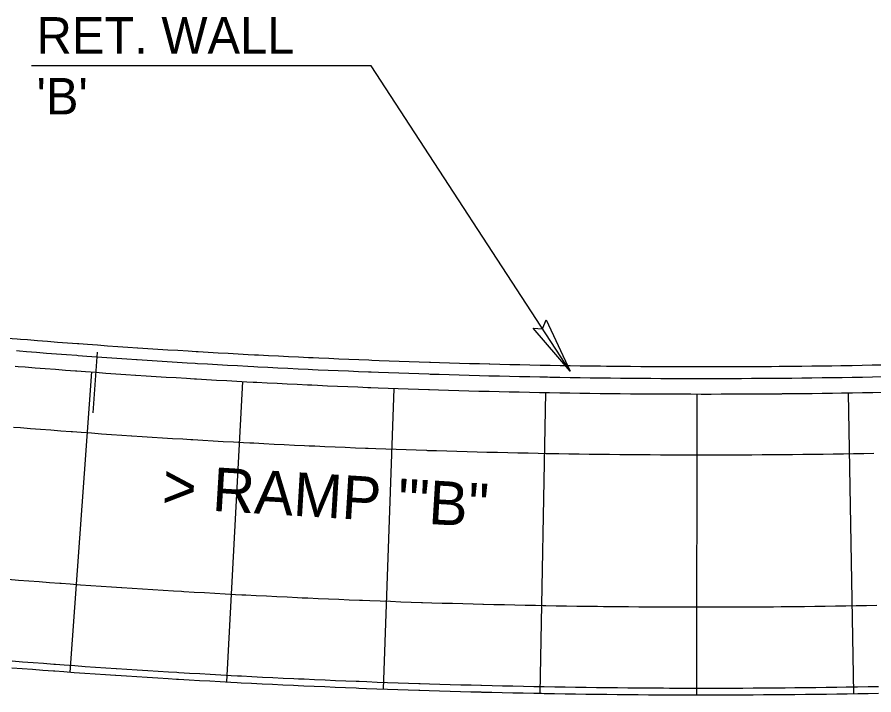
# Model space of a CAD drawing. Extents: x 2145147 to 2158018, y 137519 to 148068.
# Drawn here: x 2151017.9 to 2151102.3, y 142316.6 to 142383.4 of the extents above; entities that cross this region are included whole.
import ezdxf

# ---------------------------------------------------------------- set-up
doc = ezdxf.new("R2010")
doc.units = 0
for name, color, linetype in [('PR_Align_Ramp_B', 7, 'Continuous'), ('PR_Align_Ramp_B_Label', 7, 'Continuous'), ('PR_Align_Service_C_Leader', 7, 'Continuous'), ('PR_Align_Service_C_Txt', 7, 'Continuous'), ('PR_Arrows', 7, 'Continuous'), ('PR_Curb_Back', 7, 'Continuous'), ('PR_Curb_Face', 7, 'Continuous'), ('PR_Joint_Contraction', 7, 'Continuous'), ('PR_Joint_Long', 7, 'Continuous'), ('PR_Parapet', 7, 'Continuous'), ('PR_Retaining_Wall', 7, 'Continuous')]:
    doc.layers.add(name, color=color, linetype=linetype)

msp = doc.modelspace()

# ---------------------------------------------------------------- linework, layer by layer
at = {"layer": 'PR_Align_Ramp_B'}
msp.add_lwpolyline([(2151025.769, 142350.363), (2151025.342, 142344.378)], dxfattribs=at)
at = {"layer": 'PR_Align_Service_C_Leader'}
msp.add_lwpolyline([(2151072.395, 142348.47), (2151052.784, 142378.577), (2151019.318, 142378.577)], dxfattribs=at)
at = {"layer": 'PR_Arrows'}
msp.add_lwpolyline([(2151072.395, 142348.47), (2151068.731, 142352.723), (2151069.673, 142352.648), (2151070.02, 142353.552)], close=True, dxfattribs=at)
at = {"layer": 'PR_Curb_Back'}
msp.add_lwpolyline([(2151017.352, 142319.238), (2151018.379, 142319.158), (2151019.406, 142319.079), (2151020.433, 142319.002), (2151021.461, 142318.926), (2151021.603, 142318.915), (2151022.488, 142318.85), (2151023.516, 142318.776), (2151024.543, 142318.704), (2151025.571, 142318.632), (2151026.599, 142318.562), (2151027.593, 142318.495), (2151027.627, 142318.493), (2151028.655, 142318.425), (2151029.683, 142318.358), (2151030.711, 142318.293), (2151031.739, 142318.229), (2151032.768, 142318.166), (2151033.584, 142318.117), (2151033.796, 142318.104), (2151034.825, 142318.043), (2151035.853, 142317.984), (2151036.882, 142317.926), (2151037.91, 142317.869), (2151038.939, 142317.813), (2151039.579, 142317.779), (2151039.968, 142317.758), (2151040.997, 142317.705), (2151042.026, 142317.653), (2151043.055, 142317.602), (2151044.084, 142317.552), (2151045.113, 142317.504), (2151045.575, 142317.483), (2151046.142, 142317.457), (2151047.171, 142317.411), (2151048.2, 142317.366), (2151049.23, 142317.322), (2151050.259, 142317.28), (2151051.288, 142317.239), (2151051.574, 142317.227), (2151052.318, 142317.199), (2151053.347, 142317.16), (2151054.377, 142317.122), (2151055.407, 142317.086), (2151056.436, 142317.051), (2151057.466, 142317.017), (2151057.574, 142317.013), (2151058.496, 142316.984), (2151059.525, 142316.953), (2151060.555, 142316.922), (2151061.585, 142316.893), (2151062.615, 142316.865), (2151063.575, 142316.841), (2151063.645, 142316.839), (2151064.675, 142316.813), (2151065.705, 142316.789), (2151066.735, 142316.766), (2151067.765, 142316.744), (2151068.795, 142316.724), (2151069.577, 142316.709), (2151069.825, 142316.704), (2151070.855, 142316.686), (2151071.885, 142316.669), (2151072.915, 142316.654), (2151073.945, 142316.639), (2151074.975, 142316.626), (2151075.58, 142316.619), (2151076.005, 142316.614), (2151077.036, 142316.603), (2151078.066, 142316.593), (2151079.096, 142316.585), (2151080.126, 142316.577), (2151081.156, 142316.571), (2151081.584, 142316.569), (2151082.187, 142316.567), (2151083.217, 142316.563), (2151084.247, 142316.561), (2151085.277, 142316.56), (2151086.308, 142316.56), (2151087.338, 142316.561), (2151087.588, 142316.561), (2151088.368, 142316.563), (2151089.398, 142316.567), (2151090.429, 142316.572), (2151091.459, 142316.578), (2151092.489, 142316.585), (2151093.251, 142316.592), (2151093.519, 142316.594), (2151093.591, 142316.595), (2151094.549, 142316.604), (2151095.58, 142316.615), (2151096.61, 142316.627), (2151097.64, 142316.64), (2151098.67, 142316.655), (2151099.595, 142316.669), (2151099.7, 142316.671), (2151100.73, 142316.688), (2151101.76, 142316.706), (2151102.79, 142316.726)], dxfattribs=at)
at = {"layer": 'PR_Curb_Face'}
msp.add_lwpolyline([(2151017.404, 142319.903), (2151018.43, 142319.823), (2151019.456, 142319.744), (2151020.483, 142319.667), (2151021.51, 142319.59), (2151021.652, 142319.58), (2151022.536, 142319.515), (2151023.563, 142319.441), (2151024.59, 142319.369), (2151025.617, 142319.297), (2151026.644, 142319.227), (2151027.637, 142319.16), (2151027.671, 142319.158), (2151028.698, 142319.09), (2151029.726, 142319.024), (2151030.753, 142318.958), (2151031.781, 142318.894), (2151032.808, 142318.831), (2151033.624, 142318.782), (2151033.836, 142318.769), (2151034.863, 142318.709), (2151035.891, 142318.649), (2151036.919, 142318.591), (2151037.947, 142318.534), (2151038.975, 142318.479), (2151039.614, 142318.445), (2151040.003, 142318.424), (2151041.031, 142318.371), (2151042.059, 142318.319), (2151043.087, 142318.268), (2151044.115, 142318.218), (2151045.144, 142318.17), (2151045.606, 142318.149), (2151046.172, 142318.123), (2151047.2, 142318.077), (2151048.229, 142318.032), (2151049.257, 142317.988), (2151050.286, 142317.946), (2151051.315, 142317.905), (2151051.6, 142317.894), (2151052.343, 142317.865), (2151053.372, 142317.826), (2151054.401, 142317.788), (2151055.43, 142317.752), (2151056.459, 142317.717), (2151057.487, 142317.683), (2151057.595, 142317.68), (2151058.516, 142317.65), (2151059.545, 142317.619), (2151060.574, 142317.589), (2151061.603, 142317.56), (2151062.632, 142317.532), (2151063.592, 142317.507), (2151063.662, 142317.505), (2151064.691, 142317.48), (2151065.72, 142317.456), (2151066.749, 142317.433), (2151067.778, 142317.411), (2151068.808, 142317.39), (2151069.59, 142317.375), (2151069.837, 142317.371), (2151070.866, 142317.353), (2151071.895, 142317.336), (2151072.925, 142317.32), (2151073.954, 142317.306), (2151074.983, 142317.292), (2151075.588, 142317.285), (2151076.013, 142317.28), (2151077.042, 142317.269), (2151078.072, 142317.26), (2151079.101, 142317.251), (2151080.13, 142317.244), (2151081.16, 142317.238), (2151081.587, 142317.236), (2151082.189, 142317.233), (2151083.219, 142317.23), (2151084.248, 142317.227), (2151085.278, 142317.226), (2151086.307, 142317.226), (2151087.337, 142317.228), (2151087.586, 142317.228), (2151088.366, 142317.23), (2151089.396, 142317.234), (2151090.425, 142317.239), (2151091.454, 142317.245), (2151092.484, 142317.252), (2151093.246, 142317.258), (2151093.513, 142317.261), (2151093.586, 142317.261), (2151094.543, 142317.27), (2151095.572, 142317.281), (2151096.601, 142317.294), (2151097.631, 142317.307), (2151098.66, 142317.322), (2151099.584, 142317.336), (2151099.689, 142317.337), (2151100.719, 142317.354), (2151101.748, 142317.373), (2151102.777, 142317.392)], dxfattribs=at)
at = {"layer": 'PR_Joint_Contraction'}
for p, q in [((2151025.209, 142348.395), (2151023.091, 142318.804)), ((2151040.108, 142347.457), (2151038.514, 142317.833)), ((2151055.022, 142346.782), (2151053.952, 142317.134)), ((2151069.947, 142346.371), (2151069.39, 142316.713)), ((2151099.803, 142346.34), (2151100.305, 142316.677)), ((2151084.874, 142346.223), (2151084.852, 142316.557))]:
    msp.add_line(p, q, dxfattribs=at)
at = {"layer": 'PR_Joint_Long'}
for points in [[(2151017.516, 142342.966), (2151018.204, 142342.911), (2151019.203, 142342.832), (2151020.202, 142342.755), (2151021.201, 142342.678), (2151022.201, 142342.602), (2151023.2, 142342.528), (2151023.34, 142342.518), (2151024.2, 142342.455), (2151025.2, 142342.383), (2151026.2, 142342.312), (2151027.2, 142342.243), (2151028.2, 142342.174), (2151029.166, 142342.11), (2151029.2, 142342.107), (2151030.2, 142342.041), (2151031.2, 142341.976), (2151032.201, 142341.913), (2151033.201, 142341.85), (2151034.201, 142341.789), (2151034.996, 142341.741), (2151035.202, 142341.729), (2151036.203, 142341.67), (2151037.203, 142341.612), (2151038.204, 142341.555), (2151039.205, 142341.5), (2151040.206, 142341.446), (2151040.828, 142341.413), (2151041.207, 142341.393), (2151042.208, 142341.341), (2151043.209, 142341.29), (2151044.21, 142341.241), (2151045.211, 142341.192), (2151046.212, 142341.145), (2151046.662, 142341.124), (2151047.214, 142341.099), (2151048.215, 142341.054), (2151049.216, 142341.011), (2151050.218, 142340.968), (2151051.219, 142340.927), (2151052.221, 142340.887), (2151052.499, 142340.876), (2151053.223, 142340.848), (2151054.224, 142340.81), (2151055.226, 142340.774), (2151056.228, 142340.738), (2151057.229, 142340.704), (2151058.231, 142340.671), (2151058.337, 142340.668), (2151059.233, 142340.639), (2151060.235, 142340.609), (2151061.237, 142340.579), (2151062.239, 142340.551), (2151063.241, 142340.524), (2151064.174, 142340.5), (2151064.243, 142340.498), (2151065.245, 142340.473), (2151066.247, 142340.45), (2151067.249, 142340.427), (2151068.251, 142340.406), (2151069.253, 142340.386), (2151070.015, 142340.372), (2151070.256, 142340.367), (2151071.258, 142340.349), (2151072.26, 142340.333), (2151073.262, 142340.318), (2151074.264, 142340.304), (2151075.267, 142340.291), (2151075.855, 142340.284), (2151076.269, 142340.279), (2151077.271, 142340.268), (2151078.274, 142340.259), (2151079.276, 142340.251), (2151080.278, 142340.244), (2151081.28, 142340.238), (2151081.697, 142340.236), (2151082.283, 142340.233), (2151083.285, 142340.23), (2151084.288, 142340.227), (2151085.29, 142340.226), (2151086.292, 142340.226), (2151087.294, 142340.227), (2151087.538, 142340.228), (2151088.297, 142340.23), (2151089.299, 142340.234), (2151090.302, 142340.238), (2151091.304, 142340.244), (2151092.306, 142340.251), (2151093.048, 142340.257), (2151093.309, 142340.26), (2151093.38, 142340.26), (2151094.311, 142340.269), (2151095.313, 142340.28), (2151096.316, 142340.292), (2151097.318, 142340.305), (2151098.32, 142340.319), (2151099.22, 142340.333), (2151099.323, 142340.334), (2151100.325, 142340.351), (2151101.327, 142340.369), (2151102.329, 142340.388)], [(2151017.013, 142327.959), (2151018.029, 142327.878), (2151019.046, 142327.799), (2151020.063, 142327.721), (2151021.081, 142327.644), (2151022.097, 142327.569), (2151022.24, 142327.558), (2151023.115, 142327.494), (2151024.132, 142327.421), (2151025.15, 142327.349), (2151026.168, 142327.278), (2151027.185, 142327.209), (2151028.168, 142327.143), (2151028.203, 142327.14), (2151029.221, 142327.073), (2151030.239, 142327.007), (2151031.257, 142326.942), (2151032.275, 142326.879), (2151033.293, 142326.816), (2151034.101, 142326.768), (2151034.311, 142326.755), (2151035.329, 142326.695), (2151036.348, 142326.636), (2151037.366, 142326.579), (2151038.384, 142326.522), (2151039.403, 142326.467), (2151040.036, 142326.434), (2151040.422, 142326.413), (2151041.44, 142326.36), (2151042.459, 142326.309), (2151043.478, 142326.258), (2151044.497, 142326.209), (2151045.515, 142326.161), (2151045.973, 142326.14), (2151046.535, 142326.114), (2151047.553, 142326.069), (2151048.572, 142326.024), (2151049.592, 142325.981), (2151050.611, 142325.939), (2151051.629, 142325.899), (2151051.913, 142325.887), (2151052.649, 142325.859), (2151053.668, 142325.821), (2151054.688, 142325.783), (2151055.707, 142325.747), (2151056.727, 142325.713), (2151057.746, 142325.679), (2151057.853, 142325.676), (2151058.766, 142325.647), (2151059.785, 142325.615), (2151060.805, 142325.585), (2151061.824, 142325.557), (2151062.844, 142325.529), (2151063.794, 142325.504), (2151063.864, 142325.503), (2151064.883, 142325.477), (2151065.903, 142325.454), (2151066.923, 142325.431), (2151067.943, 142325.409), (2151068.962, 142325.389), (2151069.737, 142325.374), (2151069.983, 142325.37), (2151071.002, 142325.352), (2151072.022, 142325.335), (2151073.042, 142325.319), (2151074.062, 142325.305), (2151075.082, 142325.292), (2151075.681, 142325.285), (2151076.102, 142325.28), (2151077.122, 142325.269), (2151078.142, 142325.259), (2151079.162, 142325.251), (2151080.182, 142325.244), (2151081.202, 142325.238), (2151081.625, 142325.236), (2151082.222, 142325.233), (2151083.242, 142325.23), (2151084.262, 142325.227), (2151085.282, 142325.226), (2151086.302, 142325.226), (2151087.322, 142325.228), (2151087.57, 142325.228), (2151088.342, 142325.23), (2151089.362, 142325.234), (2151090.382, 142325.238), (2151091.402, 142325.245), (2151092.422, 142325.252), (2151093.177, 142325.258), (2151093.442, 142325.26), (2151093.514, 142325.261), (2151094.462, 142325.27), (2151095.482, 142325.281), (2151096.502, 142325.293), (2151097.522, 142325.306), (2151098.542, 142325.321), (2151099.457, 142325.335), (2151099.562, 142325.336), (2151100.582, 142325.353), (2151101.602, 142325.371), (2151102.621, 142325.391)]]:
    msp.add_lwpolyline(points, dxfattribs=at)
at = {"layer": 'PR_Parapet'}
msp.add_lwpolyline([(2151017.687, 142348.969), (2151017.996, 142348.944), (2151018.679, 142348.889), (2151019.672, 142348.811), (2151020.664, 142348.733), (2151021.656, 142348.657), (2151022.649, 142348.582), (2151023.641, 142348.509), (2151023.779, 142348.498), (2151024.634, 142348.436), (2151025.627, 142348.365), (2151026.619, 142348.294), (2151027.612, 142348.225), (2151028.605, 142348.157), (2151029.565, 142348.093), (2151029.598, 142348.091), (2151030.591, 142348.025), (2151031.585, 142347.961), (2151032.578, 142347.897), (2151033.571, 142347.835), (2151034.565, 142347.775), (2151035.354, 142347.727), (2151035.558, 142347.715), (2151036.552, 142347.656), (2151037.545, 142347.599), (2151038.539, 142347.543), (2151039.533, 142347.488), (2151040.527, 142347.434), (2151041.145, 142347.401), (2151041.521, 142347.381), (2151042.515, 142347.33), (2151043.509, 142347.279), (2151044.503, 142347.23), (2151045.497, 142347.182), (2151046.491, 142347.135), (2151046.938, 142347.115), (2151047.485, 142347.09), (2151048.48, 142347.045), (2151049.474, 142347.002), (2151050.468, 142346.96), (2151051.463, 142346.919), (2151052.457, 142346.879), (2151052.733, 142346.868), (2151053.452, 142346.84), (2151054.446, 142346.803), (2151055.441, 142346.766), (2151056.436, 142346.731), (2151057.43, 142346.697), (2151058.425, 142346.665), (2151058.529, 142346.661), (2151059.42, 142346.633), (2151060.415, 142346.603), (2151061.41, 142346.573), (2151062.405, 142346.545), (2151063.399, 142346.518), (2151064.327, 142346.494), (2151064.394, 142346.493), (2151065.389, 142346.468), (2151066.384, 142346.445), (2151067.379, 142346.422), (2151068.375, 142346.401), (2151069.37, 142346.382), (2151070.126, 142346.367), (2151070.365, 142346.363), (2151071.36, 142346.345), (2151072.355, 142346.329), (2151073.35, 142346.314), (2151074.345, 142346.3), (2151075.341, 142346.287), (2151075.925, 142346.28), (2151076.336, 142346.275), (2151077.331, 142346.265), (2151078.326, 142346.255), (2151079.322, 142346.247), (2151080.317, 142346.24), (2151081.312, 142346.234), (2151081.725, 142346.232), (2151082.307, 142346.23), (2151083.303, 142346.226), (2151084.298, 142346.224), (2151085.293, 142346.223), (2151086.289, 142346.223), (2151087.284, 142346.224), (2151087.525, 142346.225), (2151088.279, 142346.227), (2151089.274, 142346.23), (2151090.27, 142346.235), (2151091.265, 142346.241), (2151092.26, 142346.248), (2151092.997, 142346.254), (2151093.255, 142346.256), (2151093.325, 142346.257), (2151094.251, 142346.266), (2151095.246, 142346.276), (2151096.241, 142346.288), (2151097.236, 142346.301), (2151098.232, 142346.315), (2151099.125, 142346.329), (2151099.227, 142346.33), (2151100.222, 142346.347), (2151101.217, 142346.364), (2151102.212, 142346.383), (2151103.207, 142346.403)], dxfattribs=at)
at = {"layer": 'PR_Retaining_Wall'}
for points in [[(2151016.916, 142351.741), (2151017.905, 142351.66), (2151018.213, 142351.636), (2151018.894, 142351.581), (2151019.883, 142351.503), (2151020.872, 142351.426), (2151021.861, 142351.35), (2151022.85, 142351.275), (2151023.84, 142351.202), (2151023.977, 142351.192), (2151024.829, 142351.129), (2151025.819, 142351.058), (2151026.808, 142350.988), (2151027.798, 142350.919), (2151028.788, 142350.852), (2151029.745, 142350.787), (2151029.778, 142350.785), (2151030.768, 142350.72), (2151031.758, 142350.656), (2151032.748, 142350.593), (2151033.738, 142350.531), (2151034.728, 142350.47), (2151035.515, 142350.423), (2151035.719, 142350.411), (2151036.709, 142350.352), (2151037.7, 142350.295), (2151038.69, 142350.239), (2151039.681, 142350.184), (2151040.671, 142350.131), (2151041.287, 142350.098), (2151041.662, 142350.078), (2151042.653, 142350.027), (2151043.644, 142349.976), (2151044.635, 142349.927), (2151045.626, 142349.88), (2151046.617, 142349.833), (2151047.062, 142349.812), (2151047.608, 142349.787), (2151048.599, 142349.743), (2151049.59, 142349.7), (2151050.581, 142349.658), (2151051.572, 142349.617), (2151052.564, 142349.577), (2151052.838, 142349.567), (2151053.555, 142349.539), (2151054.546, 142349.501), (2151055.538, 142349.465), (2151056.529, 142349.43), (2151057.521, 142349.396), (2151058.512, 142349.364), (2151058.616, 142349.36), (2151059.504, 142349.332), (2151060.496, 142349.302), (2151061.487, 142349.273), (2151062.479, 142349.245), (2151063.471, 142349.218), (2151064.395, 142349.194), (2151064.463, 142349.192), (2151065.454, 142349.168), (2151066.446, 142349.145), (2151067.438, 142349.122), (2151068.43, 142349.101), (2151069.422, 142349.082), (2151070.176, 142349.067), (2151070.414, 142349.063), (2151071.406, 142349.045), (2151072.398, 142349.029), (2151073.39, 142349.014), (2151074.382, 142349), (2151075.374, 142348.987), (2151075.957, 142348.98), (2151076.366, 142348.976), (2151077.358, 142348.965), (2151078.35, 142348.956), (2151079.342, 142348.948), (2151080.334, 142348.941), (2151081.326, 142348.935), (2151081.738, 142348.933), (2151082.318, 142348.93), (2151083.31, 142348.927), (2151084.303, 142348.925), (2151085.295, 142348.923), (2151086.287, 142348.924), (2151087.279, 142348.925), (2151087.52, 142348.925), (2151088.271, 142348.927), (2151089.263, 142348.931), (2151090.255, 142348.935), (2151091.247, 142348.941), (2151092.239, 142348.948), (2151092.974, 142348.954), (2151093.231, 142348.957), (2151093.301, 142348.957), (2151094.224, 142348.966), (2151095.216, 142348.977), (2151096.208, 142348.988), (2151097.2, 142349.001), (2151098.192, 142349.015), (2151099.082, 142349.029), (2151099.184, 142349.031), (2151100.176, 142349.047), (2151101.168, 142349.065), (2151102.16, 142349.083), (2151103.151, 142349.103)], [(2151017.811, 142350.497), (2151018.119, 142350.473), (2151018.801, 142350.418), (2151019.792, 142350.34), (2151020.782, 142350.263), (2151021.773, 142350.187), (2151022.763, 142350.112), (2151023.754, 142350.038), (2151023.892, 142350.028), (2151024.745, 142349.966), (2151025.736, 142349.895), (2151026.727, 142349.824), (2151027.718, 142349.756), (2151028.709, 142349.688), (2151029.667, 142349.623), (2151029.7, 142349.621), (2151030.692, 142349.556), (2151031.683, 142349.491), (2151032.675, 142349.428), (2151033.666, 142349.366), (2151034.658, 142349.306), (2151035.445, 142349.258), (2151035.649, 142349.246), (2151036.641, 142349.188), (2151037.633, 142349.13), (2151038.625, 142349.074), (2151039.617, 142349.019), (2151040.609, 142348.965), (2151041.226, 142348.933), (2151041.601, 142348.913), (2151042.593, 142348.861), (2151043.585, 142348.811), (2151044.578, 142348.762), (2151045.57, 142348.714), (2151046.562, 142348.667), (2151047.008, 142348.647), (2151047.555, 142348.622), (2151048.547, 142348.577), (2151049.54, 142348.534), (2151050.532, 142348.492), (2151051.525, 142348.451), (2151052.518, 142348.412), (2151052.793, 142348.401), (2151053.51, 142348.373), (2151054.503, 142348.336), (2151055.496, 142348.299), (2151056.489, 142348.264), (2151057.482, 142348.23), (2151058.475, 142348.198), (2151058.579, 142348.194), (2151059.468, 142348.166), (2151060.461, 142348.136), (2151061.454, 142348.107), (2151062.447, 142348.079), (2151063.44, 142348.052), (2151064.366, 142348.028), (2151064.433, 142348.026), (2151065.426, 142348.001), (2151066.42, 142347.978), (2151067.413, 142347.956), (2151068.406, 142347.935), (2151069.399, 142347.915), (2151070.154, 142347.901), (2151070.393, 142347.896), (2151071.386, 142347.879), (2151072.379, 142347.863), (2151073.373, 142347.847), (2151074.366, 142347.833), (2151075.36, 142347.821), (2151075.943, 142347.814), (2151076.353, 142347.809), (2151077.346, 142347.798), (2151078.34, 142347.789), (2151079.333, 142347.781), (2151080.327, 142347.774), (2151081.32, 142347.768), (2151081.732, 142347.766), (2151082.314, 142347.764), (2151083.307, 142347.76), (2151084.301, 142347.758), (2151085.294, 142347.757), (2151086.288, 142347.757), (2151087.281, 142347.758), (2151087.522, 142347.759), (2151088.275, 142347.76), (2151089.268, 142347.764), (2151090.261, 142347.769), (2151091.255, 142347.775), (2151092.248, 142347.782), (2151092.984, 142347.788), (2151093.242, 142347.79), (2151093.312, 142347.791), (2151094.235, 142347.799), (2151095.229, 142347.81), (2151096.222, 142347.822), (2151097.216, 142347.835), (2151098.209, 142347.849), (2151099.101, 142347.862), (2151099.202, 142347.864), (2151100.196, 142347.88), (2151101.189, 142347.898), (2151102.182, 142347.917), (2151103.176, 142347.937)]]:
    msp.add_lwpolyline(points, dxfattribs=at)

# ---------------------------------------------------------------- texts
at = {"layer": 'PR_Align_Ramp_B_Label'}
msp.add_text('> RAMP \'"B"', height=4.3, rotation=356.53663, dxfattribs=at).set_placement((2151032.096, 142335.009))
at = {"layer": 'PR_Align_Service_C_Txt'}
for s, p in [('RET. WALL', (2151019.802, 142379.784)), ("'B'", (2151019.802, 142373.784))]:
    msp.add_text(s, height=3.6, rotation=360, dxfattribs=at).set_placement(p)

doc.saveas('drawing.dxf')
